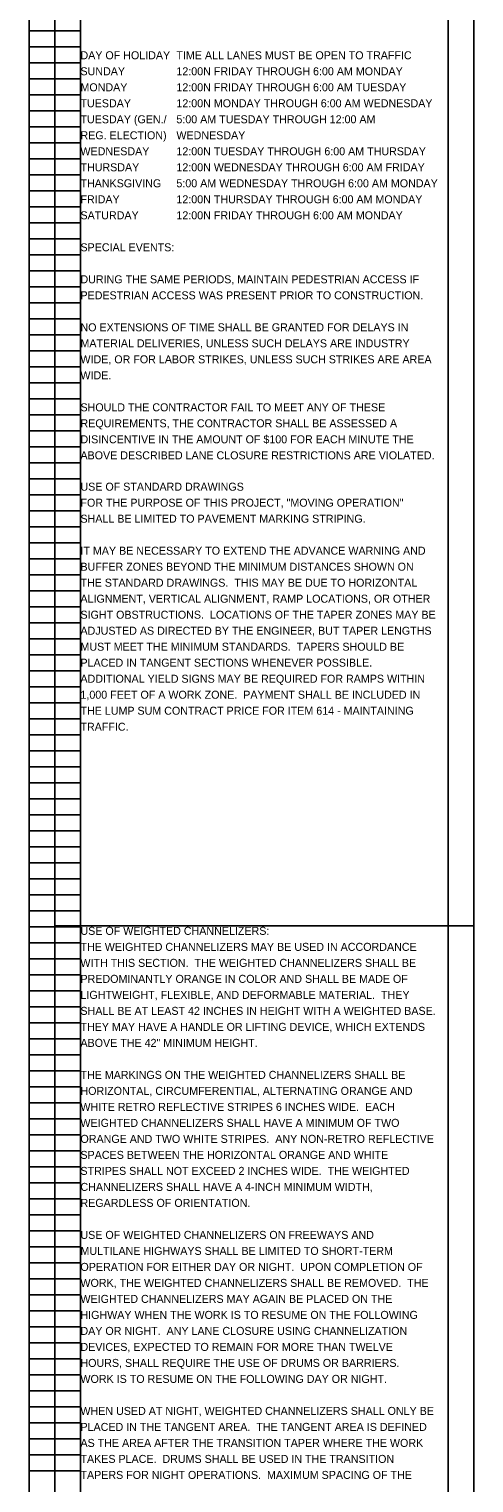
# Model space of a CAD drawing. Extents: x 0 to 19, y -301 to 22.
# Drawn here: x 1.5 to 9.29, y -28.91 to -3.47 of the extents above; entities that cross this region are included whole.
import ezdxf

# ---------------------------------------------------------------- set-up
doc = ezdxf.new("R2010")
doc.units = 0
doc.layers.add('SC_Scratch1', color=7, linetype='Continuous')
doc.layers.add('SH_Text', color=7, linetype='Continuous')

msp = doc.modelspace()

# ---------------------------------------------------------------- linework, layer by layer
at = {"layer": 'SC_Scratch1'}
for p, q in [((1.5, -19.18), (1.5, 0.98)), ((2.4, -19.18), (2.4, 0.98)), ((8.84, -19.18), (8.84, 0.98)), ((1.5, -3.5), (2.4, -3.5)), ((1.5, -3.78), (2.4, -3.78)), ((1.5, -4.06), (2.4, -4.06)), ((1.5, -4.34), (2.4, -4.34)), ((1.5, -4.62), (2.4, -4.62)), ((1.5, -4.9), (2.4, -4.9)), ((1.5, -5.18), (2.4, -5.18)), ((1.5, -5.46), (2.4, -5.46)), ((1.5, -5.74), (2.4, -5.74)), ((1.5, -6.02), (2.4, -6.02)), ((1.5, -6.3), (2.4, -6.3)), ((1.5, -6.58), (2.4, -6.58)), ((1.5, -6.86), (2.4, -6.86)), ((1.5, -7.14), (2.4, -7.14)), ((1.5, -7.42), (2.4, -7.42)), ((1.5, -7.7), (2.4, -7.7)), ((1.5, -7.98), (2.4, -7.98)), ((1.5, -8.26), (2.4, -8.26)), ((1.5, -8.54), (2.4, -8.54)), ((1.5, -8.82), (2.4, -8.82)), ((1.5, -9.1), (2.4, -9.1)), ((1.5, -9.38), (2.4, -9.38)), ((1.5, -9.66), (2.4, -9.66)), ((1.5, -9.94), (2.4, -9.94)), ((1.5, -10.22), (2.4, -10.22)), ((1.5, -10.5), (2.4, -10.5)), ((1.5, -10.78), (2.4, -10.78)), ((1.5, -11.06), (2.4, -11.06)), ((1.5, -11.34), (2.4, -11.34)), ((1.5, -11.62), (2.4, -11.62)), ((1.5, -11.9), (2.4, -11.9)), ((1.5, -12.18), (2.4, -12.18)), ((1.5, -12.46), (2.4, -12.46)), ((1.5, -12.74), (2.4, -12.74)), ((1.5, -13.02), (2.4, -13.02)), ((1.5, -13.3), (2.4, -13.3)), ((1.5, -13.58), (2.4, -13.58)), ((1.5, -13.86), (2.4, -13.86)), ((1.5, -14.14), (2.4, -14.14)), ((1.5, -14.42), (2.4, -14.42)), ((1.5, -14.7), (2.4, -14.7)), ((1.5, -14.98), (2.4, -14.98)), ((1.5, -15.26), (2.4, -15.26)), ((1.5, -15.54), (2.4, -15.54)), ((1.5, -15.82), (2.4, -15.82)), ((1.5, -16.1), (2.4, -16.1)), ((1.5, -16.38), (2.4, -16.38)), ((1.5, -16.66), (2.4, -16.66)), ((1.5, -16.94), (2.4, -16.94)), ((1.5, -17.22), (2.4, -17.22)), ((1.5, -17.5), (2.4, -17.5)), ((1.5, -17.78), (2.4, -17.78)), ((1.5, -18.06), (2.4, -18.06)), ((1.5, -18.34), (2.4, -18.34)), ((1.5, -18.62), (2.4, -18.62)), ((1.5, -18.9), (2.4, -18.9)), ((1.5, -19.18), (2.4, -19.18)), ((1.5, -19.18), (2.4, -19.18)), ((1.5, -39.34), (1.5, -19.18)), ((2.4, -39.34), (2.4, -19.18)), ((8.84, -39.34), (8.84, -19.18)), ((1.5, -19.46), (2.4, -19.46)), ((1.5, -19.74), (2.4, -19.74)), ((1.5, -20.02), (2.4, -20.02)), ((1.5, -20.3), (2.4, -20.3)), ((1.5, -20.58), (2.4, -20.58)), ((1.5, -20.86), (2.4, -20.86)), ((1.5, -21.14), (2.4, -21.14)), ((1.5, -21.42), (2.4, -21.42)), ((1.5, -21.7), (2.4, -21.7)), ((1.5, -21.98), (2.4, -21.98)), ((1.5, -22.26), (2.4, -22.26)), ((1.5, -22.54), (2.4, -22.54)), ((1.5, -22.82), (2.4, -22.82)), ((1.5, -23.1), (2.4, -23.1)), ((1.5, -23.38), (2.4, -23.38)), ((1.5, -23.66), (2.4, -23.66)), ((1.5, -23.94), (2.4, -23.94)), ((1.5, -24.22), (2.4, -24.22)), ((1.5, -24.5), (2.4, -24.5)), ((1.5, -24.78), (2.4, -24.78)), ((1.5, -25.06), (2.4, -25.06)), ((1.5, -25.34), (2.4, -25.34)), ((1.5, -25.62), (2.4, -25.62)), ((1.5, -25.9), (2.4, -25.9)), ((1.5, -26.18), (2.4, -26.18)), ((1.5, -26.46), (2.4, -26.46)), ((1.5, -26.74), (2.4, -26.74)), ((1.5, -27.02), (2.4, -27.02)), ((1.5, -27.3), (2.4, -27.3)), ((1.5, -27.58), (2.4, -27.58)), ((1.5, -27.86), (2.4, -27.86)), ((1.5, -28.14), (2.4, -28.14)), ((1.5, -28.42), (2.4, -28.42)), ((1.5, -28.7), (2.4, -28.7))]:
    msp.add_line(p, q, dxfattribs=at)
for points in [[(1.95, 0.997), (9.29, 0.997), (9.29, -19.163), (1.95, -19.163)], [(1.95, -19.163), (9.29, -19.163), (9.29, -39.323), (1.95, -39.323)]]:
    msp.add_lwpolyline(points, close=True, dxfattribs=at)

# ---------------------------------------------------------------- texts
at = {"layer": 'SH_Text'}
for s, p in [('DAY OF HOLIDAY', (2.4, -3.999)), ('TIME ALL LANES MUST BE OPEN TO TRAFFIC', (4.08, -3.999)), ('SUNDAY', (2.4, -4.279)), ('12:00N FRIDAY THROUGH 6:00 AM MONDAY', (4.08, -4.279)), ('MONDAY', (2.4, -4.559)), ('12:00N FRIDAY THROUGH 6:00 AM TUESDAY', (4.08, -4.559)), ('TUESDAY', (2.4, -4.839)), ('12:00N MONDAY THROUGH 6:00 AM WEDNESDAY', (4.08, -4.839)), ('TUESDAY (GEN./', (2.4, -5.119)), ('5:00 AM TUESDAY THROUGH 12:00 AM ', (4.08, -5.119)), ('REG. ELECTION)', (2.4, -5.399)), ('WEDNESDAY', (4.08, -5.399)), ('WEDNESDAY', (2.4, -5.679)), ('12:00N TUESDAY THROUGH 6:00 AM THURSDAY', (4.08, -5.679)), ('THURSDAY', (2.4, -5.959)), ('12:00N WEDNESDAY THROUGH 6:00 AM FRIDAY', (4.08, -5.959)), ('THANKSGIVING', (2.4, -6.239)), ('5:00 AM WEDNESDAY THROUGH 6:00 AM MONDAY', (4.08, -6.239)), ('FRIDAY', (2.4, -6.519)), ('12:00N THURSDAY THROUGH 6:00 AM MONDAY', (4.08, -6.519)), ('SATURDAY', (2.4, -6.799)), ('12:00N FRIDAY THROUGH 6:00 AM MONDAY', (4.08, -6.799)), ('SPECIAL EVENTS:', (2.4, -7.359)), ('DURING THE SAME PERIODS, MAINTAIN PEDESTRIAN ACCESS IF ', (2.4, -7.919)), ('PEDESTRIAN ACCESS WAS PRESENT PRIOR TO CONSTRUCTION.', (2.4, -8.199)), ('NO EXTENSIONS OF TIME SHALL BE GRANTED FOR DELAYS IN ', (2.4, -8.759)), ('MATERIAL DELIVERIES, UNLESS SUCH DELAYS ARE INDUSTRY ', (2.4, -9.039)), ('WIDE, OR FOR LABOR STRIKES, UNLESS SUCH STRIKES ARE AREA ', (2.4, -9.319)), ('WIDE.', (2.4, -9.599)), ('SHOULD THE CONTRACTOR FAIL TO MEET ANY OF THESE ', (2.4, -10.159)), ('REQUIREMENTS, THE CONTRACTOR SHALL BE ASSESSED A ', (2.4, -10.439)), ('DISINCENTIVE IN THE AMOUNT OF $100 FOR EACH MINUTE THE ', (2.4, -10.719)), ('ABOVE DESCRIBED LANE CLOSURE RESTRICTIONS ARE VIOLATED.', (2.4, -10.999)), ('USE OF STANDARD DRAWINGS', (2.4, -11.548)), ('FOR THE PURPOSE OF THIS PROJECT, "MOVING OPERATION" ', (2.4, -11.828)), ('SHALL BE LIMITED TO PAVEMENT MARKING STRIPING.', (2.4, -12.108)), ('IT MAY BE NECESSARY TO EXTEND THE ADVANCE WARNING AND ', (2.4, -12.668)), ('BUFFER ZONES BEYOND THE MINIMUM DISTANCES SHOWN ON ', (2.4, -12.948)), ('THE STANDARD DRAWINGS.  THIS MAY BE DUE TO HORIZONTAL ', (2.4, -13.228)), ('ALIGNMENT, VERTICAL ALIGNMENT, RAMP LOCATIONS, OR OTHER ', (2.4, -13.508)), ('SIGHT OBSTRUCTIONS.  LOCATIONS OF THE TAPER ZONES MAY BE ', (2.4, -13.788)), ('ADJUSTED AS DIRECTED BY THE ENGINEER, BUT TAPER LENGTHS ', (2.4, -14.068)), ('MUST MEET THE MINIMUM STANDARDS.  TAPERS SHOULD BE ', (2.4, -14.348)), ('PLACED IN TANGENT SECTIONS WHENEVER POSSIBLE.  ', (2.4, -14.628)), ('ADDITIONAL YIELD SIGNS MAY BE REQUIRED FOR RAMPS WITHIN ', (2.4, -14.908)), ('1,000 FEET OF A WORK ZONE.  PAYMENT SHALL BE INCLUDED IN ', (2.4, -15.188)), ('THE LUMP SUM CONTRACT PRICE FOR ITEM 614 - MAINTAINING ', (2.4, -15.468)), ('TRAFFIC.', (2.4, -15.748)), ('USE OF WEIGHTED CHANNELIZERS:', (2.4, -19.32)), ('THE WEIGHTED CHANNELIZERS MAY BE USED IN ACCORDANCE ', (2.4, -19.6)), ('WITH THIS SECTION.  THE WEIGHTED CHANNELIZERS SHALL BE ', (2.4, -19.88)), ('PREDOMINANTLY ORANGE IN COLOR AND SHALL BE MADE OF ', (2.4, -20.16)), ('LIGHTWEIGHT, FLEXIBLE, AND DEFORMABLE MATERIAL.  THEY ', (2.4, -20.44)), ('SHALL BE AT LEAST 42 INCHES IN HEIGHT WITH A WEIGHTED BASE.  ', (2.4, -20.72)), ('THEY MAY HAVE A HANDLE OR LIFTING DEVICE, WHICH EXTENDS ', (2.4, -21)), ('ABOVE THE 42" MINIMUM HEIGHT.', (2.4, -21.28)), ('THE MARKINGS ON THE WEIGHTED CHANNELIZERS SHALL BE ', (2.4, -21.84)), ('HORIZONTAL, CIRCUMFERENTIAL, ALTERNATING ORANGE AND ', (2.4, -22.12)), ('WHITE RETRO REFLECTIVE STRIPES 6 INCHES WIDE.  EACH ', (2.4, -22.4)), ('WEIGHTED CHANNELIZERS SHALL HAVE A MINIMUM OF TWO ', (2.4, -22.68)), ('ORANGE AND TWO WHITE STRIPES.  ANY NON-RETRO REFLECTIVE ', (2.4, -22.96)), ('SPACES BETWEEN THE HORIZONTAL ORANGE AND WHITE ', (2.4, -23.24)), ('STRIPES SHALL NOT EXCEED 2 INCHES WIDE.  THE WEIGHTED ', (2.4, -23.52)), ('CHANNELIZERS SHALL HAVE A 4-INCH MINIMUM WIDTH, ', (2.4, -23.8)), ('REGARDLESS OF ORIENTATION.', (2.4, -24.08)), ('USE OF WEIGHTED CHANNELIZERS ON FREEWAYS AND ', (2.4, -24.64)), ('MULTILANE HIGHWAYS SHALL BE LIMITED TO SHORT-TERM ', (2.4, -24.92)), ('OPERATION FOR EITHER DAY OR NIGHT.  UPON COMPLETION OF ', (2.4, -25.2)), ('WORK, THE WEIGHTED CHANNELIZERS SHALL BE REMOVED.  THE ', (2.4, -25.48)), ('WEIGHTED CHANNELIZERS MAY AGAIN BE PLACED ON THE ', (2.4, -25.76)), ('HIGHWAY WHEN THE WORK IS TO RESUME ON THE FOLLOWING ', (2.4, -26.04)), ('DAY OR NIGHT.  ANY LANE CLOSURE USING CHANNELIZATION ', (2.4, -26.32)), ('DEVICES, EXPECTED TO REMAIN FOR MORE THAN TWELVE ', (2.4, -26.6)), ('HOURS, SHALL REQUIRE THE USE OF DRUMS OR BARRIERS.  ', (2.4, -26.88)), ('WORK IS TO RESUME ON THE FOLLOWING DAY OR NIGHT.', (2.4, -27.16)), ('WHEN USED AT NIGHT, WEIGHTED CHANNELIZERS SHALL ONLY BE ', (2.4, -27.72)), ('PLACED IN THE TANGENT AREA.  THE TANGENT AREA IS DEFINED ', (2.4, -28)), ('AS THE AREA AFTER THE TRANSITION TAPER WHERE THE WORK ', (2.4, -28.28)), ('TAKES PLACE.  DRUMS SHALL BE USED IN THE TRANSITION ', (2.4, -28.56)), ('TAPERS FOR NIGHT OPERATIONS.  MAXIMUM SPACING OF THE ', (2.4, -28.84))]:
    msp.add_text(s, height=0.14, dxfattribs=at).set_placement(p)

doc.saveas('drawing.dxf')
